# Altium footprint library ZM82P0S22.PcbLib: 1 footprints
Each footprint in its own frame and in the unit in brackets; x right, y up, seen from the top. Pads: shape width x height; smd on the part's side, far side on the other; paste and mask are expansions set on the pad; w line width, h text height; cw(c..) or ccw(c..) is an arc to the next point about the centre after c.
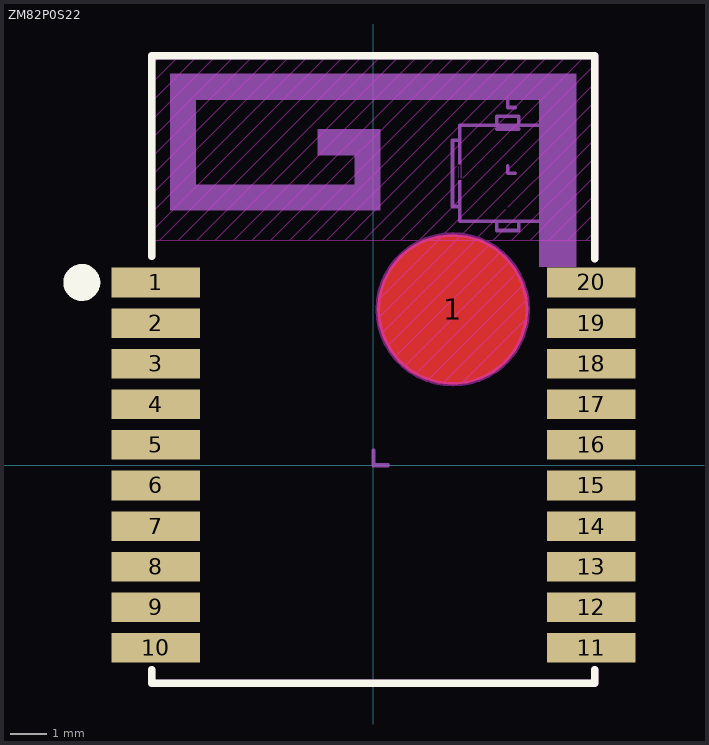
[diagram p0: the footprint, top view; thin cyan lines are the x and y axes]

## ZM82P0S22 [mm]
pads (23):
  rect 2.4x0.8 smd mask+0.051: 1(-5.9,4.95) 2(-5.9,3.85) 3(-5.9,2.75) 4(-5.9,1.65) 5(-5.9,0.55) 6(-5.9,-0.55) 7(-5.9,-1.65) 8(-5.9,-2.75) 9(-5.9,-3.85) 10(-5.9,-4.95) 11(5.9,-4.95) 12(5.9,-3.85) 13(5.9,-2.75) 14(5.9,-1.65) 15(5.9,-0.55) 16(5.9,0.55) 17(5.9,1.65) 18(5.9,2.75) 19(5.9,3.85) 20(5.9,4.95)
  round 1.016 on Mech15 paste-0.508 mask+0.381: 1(2.15,4.221)
  rect 0.75x1.8 on Mech15 mask+0: 1(2.36,7.925)
  rect 0.6x1.14 on Mech15 mask+0: 1(3.642,6.828)
Top Layer:
  pour cut-out: 0.11,4.221 0.149,3.823 0.265,3.44 0.454,3.088 0.708,2.779 1.017,2.525 1.369,2.336 1.752,2.22 2.15,2.181 2.548,2.22 2.93,2.336 3.283,2.525 3.592,2.779 3.846,3.088 4.034,3.44 4.151,3.823 4.19,4.221 4.151,4.619 4.034,5.002 3.846,5.354 3.592,5.663 3.283,5.917 2.93,6.106 2.548,6.222 2.15,6.261 1.752,6.222 1.369,6.106 1.017,5.917 0.708,5.663 0.454,5.354 0.265,5.002 0.149,4.619
Top Layer keep-out:
  circle w0.127: c2.15,4.221 r2.03
  lines w0.025: 0.149,3.992 2.396,6.238 ; 0.156,4.5 1.889,6.234 ; 0.243,3.584 2.814,6.155 ; 0.394,3.233 3.162,6 ; 0.582,2.918 3.453,5.789 ; 0.833,2.667 3.704,5.538 ; 1.135,2.467 3.907,5.239 ; 1.476,2.306 4.062,4.892 ; 1.886,2.214 4.171,4.498 ; 2.358,2.183 4.188,4.013
Top Overlay:
  circle w0.5: c-7.9,4.95 r0.25
  lines w0.2: -6,-5.54 -6,-5.91 6,-5.91 6,-5.54 ; -6,5.661 -6,11.09 6,11.09 6,5.585
Keep-Out Layer:
  lines w0.025: -5.999,6.334 -1.243,11.09 ; -5.998,6.837 -1.745,11.09 ; -5.998,7.339 -2.248,11.09 ; -5.998,7.841 -2.75,11.09 ; -5.998,8.344 -3.252,11.09 ; -5.998,8.846 -3.754,11.09 ; -5.998,9.348 -4.256,11.09 ; -5.998,9.85 -4.758,11.09 ; -5.998,10.352 -5.26,11.09 ; -5.998,10.854 -5.763,11.09 ; -5.787,6.09 -0.787,11.09 ; -5.284,6.09 -0.285,11.09 ; -4.782,6.09 0.218,11.09 ; -4.28,6.09 0.72,11.09 ; -3.778,6.09 1.222,11.09 ; -3.276,6.09 1.724,11.09 ; -2.774,6.09 2.226,11.09 ; -2.272,6.09 2.728,11.09 ; -1.77,6.09 3.23,11.09 ; -1.267,6.09 3.733,11.09 ; -0.765,6.09 4.235,11.09 ; -0.263,6.09 4.737,11.09 ; 0.239,6.09 5.241,11.092 ; 0.741,6.09 5.741,11.089 ; 1.243,6.09 5.999,10.846 ; 1.745,6.09 5.998,10.343 ; 2.248,6.09 5.998,9.841 ; 2.75,6.09 5.998,9.339 ; 3.252,6.09 5.998,8.836 ; 3.754,6.09 5.998,8.334 ; 4.256,6.09 5.998,7.832 ; 4.758,6.09 5.998,7.33 ; 5.26,6.09 5.998,6.828 ; 5.763,6.09 5.998,6.326 ; -6,6.09 6,6.09 6,11.09 -6,11.09 -6,6.09
Mechanical 15:
  region: 0.192,9.101 -1.508,9.101 -1.508,8.401 -0.508,8.401 -0.508,7.601 -4.808,7.601 -4.808,9.901 4.491,9.901 4.491,5.382 5.491,5.382 5.491,10.601 -5.508,10.601 -5.508,6.901 0.192,6.901
  lines w0.1: 2.342,7.008 2.142,7.008 2.142,8.808 2.342,8.808 ; 3.342,6.608 3.342,6.358 3.942,6.358 3.942,6.608 ; 3.342,9.108 3.942,9.108 ; 3.342,9.208 3.342,9.458 3.942,9.458 3.942,9.208 ; 3.642,8.108 3.642,7.908 3.842,7.908 ; 3.642,9.893 3.642,9.693 3.842,9.693 ; 4.942,7.008 5.142,7.008 5.142,8.808 4.942,8.808 ; 2.342,6.608 2.342,9.208 4.942,9.208 4.942,6.608 2.342,6.608
  lines w0.114: 0,0.4 0,0 0.4,0
  lines w0.2: -6,-5.54 -6,-5.91 6,-5.91 6,-5.54 ; -6,5.661 -6,11.09 6,11.09 6,5.585
  text "各层禁止走线" at -3.111,6.368 h0.76
  text "天线区域" at -2.332,7.275 h0.76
